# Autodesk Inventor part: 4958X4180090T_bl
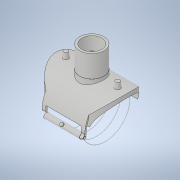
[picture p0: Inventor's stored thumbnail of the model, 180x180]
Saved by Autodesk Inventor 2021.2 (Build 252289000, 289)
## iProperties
Created: 2020-06
Part Number: 4958X4180090T_bl
Material: Generic
Description: Plasson Branch Saddle 180x90
Document SubType Name: Modeling
Designer: KIM
Density: 1 g/cm^3
Appearance: Default
Author: KIM
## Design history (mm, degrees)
derived "4958X4.ipt"
feature "Solid1::4958X4.ipt" dims "ScaleForDerivedMember" = 10
tag "TaggingFeature1"
body "Solid1"
other parameters: "d0" = 263 [user parameter], "d3" = 209.4 [user parameter], "d4" = 107 [user parameter], "d7" = 73 [user parameter], "d9" = 81 [user parameter], "d10" = 0.5 [user parameter], "d11" = 1 [user parameter], "d12" = 26.75 [user parameter], "d13" = 16 [user parameter], "d14" = 8 [user parameter], "d16" = 10 deg [user parameter], "d17" = 10 deg [user parameter], "d19" = 0 [user parameter], "d23" = 0 [user parameter], "d26" = 0 [user parameter], "d27" = 157.8 [user parameter], "d28" = 0 [user parameter], "d29" = 131.5 [user parameter], "d30" = 0 [user parameter], "d31" = 1 [user parameter], "d32" = 1 [user parameter], "d33" = 19.2 [user parameter], "d34" = 9.6 [user parameter], "d35" = 45 deg [user parameter], "d36" = 131.5 [user parameter], "d37" = 0 [user parameter], "d38" = 5 [user parameter], "d39" = 85 deg [user parameter], "d40" = 26.75 [user parameter], "d41" = 16 [user parameter], "d42" = 95.63636 [user parameter], "d49" = 3 [user parameter], "d50" = 6 [user parameter], "d51" = 5 [user parameter], "d54" = 0 [user parameter], "d57" = 35 deg [user parameter], "d60" = 16.4375 [user parameter], "d61" = 1 [user parameter], "d62" = 90 deg [user parameter], "d63" = 2 [user parameter], "d64" = 0 [user parameter], "d65" = 0 [user parameter], "d68" = 32.875 [user parameter], "d70" = 0.57711 [user parameter], "d71" = 10 deg [user parameter], "d73" = 5.145 [user parameter], "B" = 229 [user parameter], "L" = 263 [user parameter], "LS" = 81 [user parameter], "H1" = 107 [user parameter], "Dt" = 16 [user parameter], "di" = 73 [user parameter], "d72" = 14.7 [user parameter]
